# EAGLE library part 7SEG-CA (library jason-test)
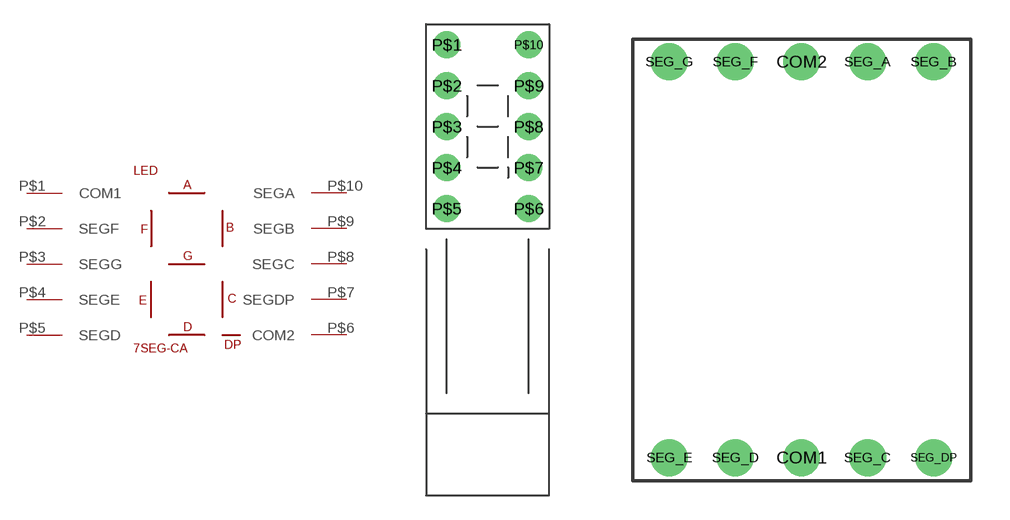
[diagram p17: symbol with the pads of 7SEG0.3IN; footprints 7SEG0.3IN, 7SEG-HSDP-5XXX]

Designator prefix LED

## 7SEG-CAR/A  [7SEG0.3IN]
P$1  COM1
P$2  SEGF
P$3  SEGG
P$4  SEGE
P$5  SEGD
P$6  COM2
P$7  SEGDP
P$8  SEGC
P$9  SEGB
P$10  SEGA

## 7SEG-CATH  [7SEG-HSDP-5XXX]
COM1  COM1
COM2  COM2
SEG_A  SEGA
SEG_B  SEGB
SEG_C  SEGC
SEG_D  SEGD
SEG_DP  SEGDP
SEG_E  SEGE
SEG_F  SEGF
SEG_G  SEGG

## 7SEG-CASMT-WRAP  [7SEG-HDSP-5XXX-SMT]
Pads as for 7SEG-HSDP-5XXX

## Footprint 7SEG0.3IN (pad centres in mm)
7-segment display, 0.3" wide
drill 0.9 pad 1.676 round: P$1 0,0; P$2 0,-2.54; P$3 0,-5.08; P$4 0,-7.62; P$5 0,-10.16; P$6 5.08,-10.16; P$7 5.08,-7.62; P$8 5.08,-5.08; P$9 5.08,-2.54; P$10 5.08,0

## Footprint 7SEG-HSDP-5XXX (pad centres in mm)
drill 0.8 pad 1.422 round: COM1 0,-7.62; COM2 0,7.62; SEG_A 2.54,7.62; SEG_B 5.08,7.62; SEG_C 2.54,-7.62; SEG_D -2.54,-7.62; SEG_DP 5.08,-7.62; SEG_E -5.08,-7.62; SEG_F -2.54,7.62; SEG_G -5.08,7.62

## Footprint 7SEG-HDSP-5XXX-SMT (pad centres in mm)
smd 1.27 x 2.54 bottom: COM1 0,-6.35; COM2 0,6.35; SEG_A 2.54,6.35; SEG_B 5.08,6.35; SEG_C 2.54,-6.35; SEG_D -2.54,-6.35; SEG_DP 5.08,-6.35; SEG_E -5.08,-6.35; SEG_F -2.54,6.35; SEG_G -5.08,6.35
